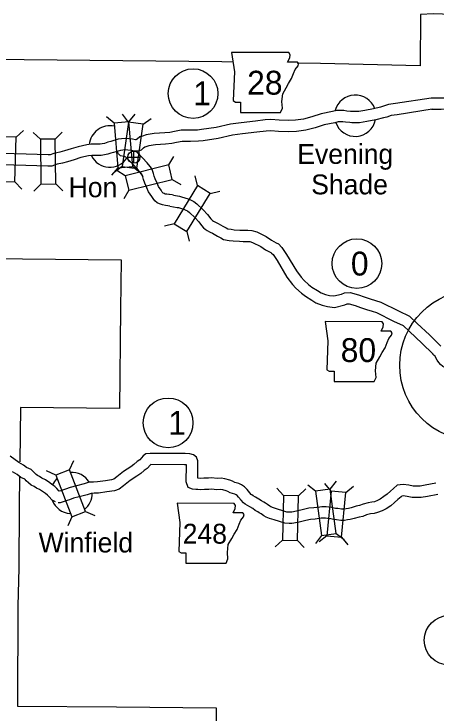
# Model space of a CAD drawing. Extents: x 1382482 to 1385815, y 1168351 to 1170484.
# Drawn here: x 1382910.5 to 1383022.7, y 1169947.1 to 1170133.1 of the extents above; entities that cross this region are included whole.
import ezdxf

# ---------------------------------------------------------------- set-up
doc = ezdxf.new("R2010")
doc.units = 0
for name, color, linetype in [('10', 7, 'Continuous'), ('20', 7, 'Continuous'), ('21', 7, 'Continuous'), ('24', 7, 'Continuous'), ('26', 7, 'Continuous'), ('8', 7, 'Continuous'), ('Default', 7, 'Continuous'), ('R_Draft', 7, 'Continuous')]:
    doc.layers.add(name, color=color, linetype=linetype)

msp = doc.modelspace()

# ---------------------------------------------------------------- linework, layer by layer
at = {"layer": '10'}
for points in [[(1383055.26, 1170107.05), (1383051.22, 1170107.22), (1383050.81, 1170107.46), (1383050.16, 1170107.88), (1383048.32, 1170109.4), (1383047.15, 1170110.4), (1383046.33, 1170111.03), (1383045.14, 1170111.68), (1383044.07, 1170112.06), (1383042.75, 1170112.27), (1383041.72, 1170112.17), (1383039.08, 1170112.1), (1383036.98, 1170112.15), (1383035.13, 1170111.99), (1383033.27, 1170111.77), (1383031.03, 1170111.4), (1383029.05, 1170111.26), (1383027.2, 1170111.01), (1383025.69, 1170110.79), (1383023.97, 1170110.76), (1383021.34, 1170110.78)], [(1383021.34, 1170110.78), (1383011.87, 1170109.34), (1383010.05, 1170109.08), (1383008.68, 1170108.63), (1383007.88, 1170108.39), (1383006.03, 1170107.91), (1383003.74, 1170107.49), (1383002.1, 1170107.2), (1383000.37, 1170107.24), (1382999.93, 1170107.26), (1382998.91, 1170107.35), (1382998.13, 1170107.46), (1382996.28, 1170107.45), (1382995.1, 1170107.19), (1382992.16, 1170106.61), (1382989.66, 1170105.78), (1382987.47, 1170105.21), (1382985.31, 1170104.93), (1382983.38, 1170104.81), (1382980.94, 1170104.94), (1382978.74, 1170105.12), (1382977.23, 1170104.99), (1382974.66, 1170104.68), (1382970.86, 1170104.23), (1382968.04, 1170103.86), (1382964.18, 1170103.01), (1382960.35, 1170102.43), (1382959.25, 1170102.3), (1382957.35, 1170102.24), (1382954.89, 1170102.22), (1382953.1, 1170101.95), (1382951.9, 1170101.65), (1382950.55, 1170101.54), (1382947.73, 1170101.37), (1382945.61, 1170100.98), (1382944.63, 1170100.68), (1382943.9, 1170100.45), (1382943.16, 1170099.9), (1382942.96, 1170099.76), (1382942.9, 1170099.72), (1382942.8, 1170099.72), (1382941.95, 1170099.84), (1382940.96, 1170099.98), (1382940.13, 1170100.02), (1382939.08, 1170099.93), (1382938.14, 1170099.84), (1382936.16, 1170099.21), (1382935.38, 1170099.06), (1382934.56, 1170098.76), (1382933.92, 1170098.64), (1382933.34, 1170098.52), (1382932.36, 1170098.55), (1382930.97, 1170098.5), (1382929.82, 1170098.37), (1382927.48, 1170097.87), (1382925.61, 1170097.28), (1382923.84, 1170096.76), (1382922.62, 1170096.43), (1382921.05, 1170096.09), (1382920.05, 1170095.71)], [(1383055.38, 1170104.04), (1383050.67, 1170104.24), (1383049.96, 1170104.47), (1383049.23, 1170104.91), (1383048.38, 1170105.46), (1383046.39, 1170107.1), (1383045.25, 1170108.07), (1383044.68, 1170108.51), (1383043.91, 1170108.93), (1383043.32, 1170109.14), (1383042.66, 1170109.25), (1383041.9, 1170109.17), (1383039.08, 1170109.1), (1383037.07, 1170109.14), (1383035.43, 1170109), (1383033.69, 1170108.8), (1383031.38, 1170108.41), (1383029.35, 1170108.27), (1383027.61, 1170108.04), (1383025.94, 1170107.8), (1383023.99, 1170107.75), (1383021.43, 1170107.78)], [(1383021.67, 1170107.8), (1383012.31, 1170106.38), (1383010.74, 1170106.14), (1383009.57, 1170105.76), (1383008.68, 1170105.5), (1383006.68, 1170104.98), (1383004.27, 1170104.54), (1383002.33, 1170104.19), (1383000.26, 1170104.24), (1382999.73, 1170104.27), (1382998.57, 1170104.37), (1382997.93, 1170104.46), (1382996.62, 1170104.46), (1382995.72, 1170104.25), (1382992.93, 1170103.7), (1382990.51, 1170102.9), (1382988.04, 1170102.26), (1382985.6, 1170101.94), (1382983.39, 1170101.81), (1382980.74, 1170101.95), (1382978.75, 1170102.11), (1382977.54, 1170102), (1382975.01, 1170101.7), (1382971.24, 1170101.26), (1382968.56, 1170100.9), (1382964.73, 1170100.06), (1382960.75, 1170099.46), (1382959.47, 1170099.31), (1382957.41, 1170099.24), (1382955.14, 1170099.22), (1382953.69, 1170099), (1382952.38, 1170098.68), (1382950.76, 1170098.55), (1382948.1, 1170098.38), (1382946.32, 1170098.06), (1382945.53, 1170097.82), (1382945.28, 1170097.74), (1382944.92, 1170097.47), (1382944.74, 1170097.35), (1382944.29, 1170096.99), (1382943.43, 1170096.71), (1382942.58, 1170096.72), (1382941.53, 1170096.87), (1382940.68, 1170096.99), (1382940.19, 1170097.01), (1382939.35, 1170096.94), (1382938.73, 1170096.89), (1382936.91, 1170096.31), (1382936.19, 1170096.16), (1382935.36, 1170095.86), (1382934.51, 1170095.7), (1382933.61, 1170095.51), (1382932.36, 1170095.55), (1382931.19, 1170095.5), (1382930.3, 1170095.41), (1382928.24, 1170094.97), (1382926.49, 1170094.41), (1382924.66, 1170093.87), (1382923.32, 1170093.51), (1382921.9, 1170093.21), (1382920.49, 1170092.67)], [(1382920.05, 1170095.69), (1382919.58, 1170095.71), (1382913.67, 1170095.86), (1382907.29, 1170096.03)], [(1382938.76, 1170095.46), (1382938.26, 1170096), (1382938.05, 1170096.29), (1382937.97, 1170096.39), (1382937.92, 1170096.45), (1382937.78, 1170096.57)], [(1382951.87, 1170082.1), (1382951.34, 1170082.19), (1382951.32, 1170082.19), (1382950.75, 1170082.24), (1382949.91, 1170082.38), (1382949.16, 1170082.66), (1382948.55, 1170082.96), (1382947.89, 1170083.48), (1382947.46, 1170084.06), (1382947.06, 1170084.63), (1382946.25, 1170085.84), (1382945.76, 1170086.95), (1382945.21, 1170088.22), (1382944.88, 1170089.11), (1382944.7, 1170089.82), (1382944.49, 1170090.37), (1382944.35, 1170090.66), (1382944.24, 1170090.83), (1382943.6, 1170091.54), (1382942.43, 1170092.86), (1382941.54, 1170093.74), (1382940.82, 1170094.48), (1382940.57, 1170094.76), (1382940.22, 1170095.08), (1382940.15, 1170095.13), (1382940.03, 1170095.16), (1382939.71, 1170095.28), (1382938.76, 1170095.46)], [(1382952.86, 1170084.95), (1382952.47, 1170085.04), (1382951.78, 1170085.15), (1382951.66, 1170085.17), (1382951.13, 1170085.22), (1382950.68, 1170085.29), (1382950.34, 1170085.42), (1382950.15, 1170085.51), (1382950.06, 1170085.58), (1382949.89, 1170085.82), (1382949.54, 1170086.32), (1382948.89, 1170087.29), (1382948.5, 1170088.15), (1382948, 1170089.33), (1382947.75, 1170090), (1382947.57, 1170090.72), (1382947.24, 1170091.57), (1382946.98, 1170092.12), (1382946.64, 1170092.65), (1382945.84, 1170093.54), (1382944.62, 1170094.92), (1382943.67, 1170095.86), (1382943.01, 1170096.53), (1382942.85, 1170096.71)], [(1382920.49, 1170092.67), (1382919.48, 1170092.72), (1382913.59, 1170092.86), (1382907.24, 1170093.03)], [(1382952.86, 1170084.95), (1382954.44, 1170084.69), (1382954.98, 1170084.56), (1382956.73, 1170084.01), (1382957.37, 1170083.77), (1382958.25, 1170083.33), (1382959.05, 1170082.69), (1382960.78, 1170081.11), (1382961.9, 1170079.84)], [(1382951.87, 1170082.1), (1382953.86, 1170081.74), (1382954.19, 1170081.67), (1382955.76, 1170081.17), (1382956.17, 1170081.01), (1382956.62, 1170080.79), (1382957.1, 1170080.41), (1382958.64, 1170079), (1382959.58, 1170077.94)], [(1382961.9, 1170079.84), (1382962.75, 1170078.73), (1382962.93, 1170078.48), (1382963.02, 1170078.42), (1382963.27, 1170078.25), (1382963.48, 1170078.11), (1382963.81, 1170077.9), (1382964.77, 1170077.47)], [(1382959.58, 1170077.94), (1382960.35, 1170076.93), (1382960.81, 1170076.31), (1382961.31, 1170075.95), (1382961.58, 1170075.77), (1382961.84, 1170075.6), (1382962.41, 1170075.24), (1382963.4, 1170074.8)], [(1382964.77, 1170077.47), (1382966, 1170076.73), (1382966.89, 1170076.32), (1382967.29, 1170076.08), (1382968.16, 1170075.92), (1382969.02, 1170075.8), (1382970.47, 1170075.72), (1382971.5, 1170075.71), (1382972.61, 1170075.67), (1382973.71, 1170075.6), (1382974.99, 1170075.22), (1382977.54, 1170073.99), (1382978.94, 1170073.05), (1382980.16, 1170072.34), (1382980.74, 1170072.04), (1382981.67, 1170071.11), (1382982.94, 1170069.26), (1382985.53, 1170064.87), (1382986.84, 1170063.18), (1382987.57, 1170062.33), (1382988.8, 1170061.23), (1382989.65, 1170060.58), (1382991.18, 1170059.63), (1382992.09, 1170059.07), (1382993.25, 1170058.6), (1382994.38, 1170058.36), (1382995.51, 1170058.19), (1382997.52, 1170058.68), (1382998.36, 1170059.02), (1382999.82, 1170059.15), (1383002.08, 1170058.5), (1383003.58, 1170057.96), (1383005.13, 1170057.43), (1383006.58, 1170057), (1383007.95, 1170056.57), (1383012.66, 1170054.24), (1383015.64, 1170052.82), (1383017.69, 1170050.91), (1383020.97, 1170047.85), (1383023.98, 1170044.86)], [(1382963.23, 1170074.89), (1382964.6, 1170074.07), (1382965.47, 1170073.67), (1382966.2, 1170073.22), (1382967.69, 1170072.95), (1382968.75, 1170072.81), (1382970.37, 1170072.73), (1382971.42, 1170072.71), (1382972.46, 1170072.67), (1382973.18, 1170072.63), (1382973.91, 1170072.41), (1382976.05, 1170071.38), (1382977.35, 1170070.5), (1382978.7, 1170069.72), (1382978.93, 1170069.6), (1382979.36, 1170069.18), (1382980.41, 1170067.65), (1382983.04, 1170063.18), (1382984.52, 1170061.28), (1382985.42, 1170060.23), (1382986.88, 1170058.92), (1382987.94, 1170058.11), (1382989.6, 1170057.08), (1382990.74, 1170056.38), (1382992.36, 1170055.73), (1382993.84, 1170055.4), (1382995.65, 1170055.14), (1382998.44, 1170055.82), (1382999.07, 1170056.07), (1382999.53, 1170056.11), (1383001.15, 1170055.65), (1383002.58, 1170055.13), (1383004.22, 1170054.57), (1383005.71, 1170054.13), (1383006.83, 1170053.78), (1383011.35, 1170051.54), (1383013.93, 1170050.31), (1383015.64, 1170048.71), (1383018.89, 1170045.69), (1383021.86, 1170042.73)], [(1383048.25, 1170025.19), (1383036.79, 1170025.48), (1383036.15, 1170025.79), (1383035.57, 1170026.18), (1383035.18, 1170026.91), (1383034.99, 1170027.48), (1383034.91, 1170028.23), (1383035.25, 1170038.52), (1383035.26, 1170038.65), (1383035.26, 1170038.65), (1383035.14, 1170038.66), (1383034.05, 1170038.68), (1383026.55, 1170038.83), (1383025.85, 1170038.85), (1383025.14, 1170039.1), (1383024.46, 1170039.43), (1383023.88, 1170040.01), (1383023.42, 1170040.48), (1383023.01, 1170041.13), (1383022.64, 1170041.78), (1383022.41, 1170042.19), (1383022.21, 1170042.41), (1383021.92, 1170042.68), (1383021.73, 1170042.85)], [(1382922.5, 1170006.29), (1382921.86, 1170006.99), (1382921.32, 1170007.54), (1382920.52, 1170008.13), (1382919.98, 1170008.49), (1382918.8, 1170009.34), (1382917.86, 1170009.79), (1382917.22, 1170010.18), (1382916.68, 1170010.45), (1382916.34, 1170010.75), (1382915.89, 1170011.16), (1382915.58, 1170011.52), (1382914.98, 1170012.09), (1382913.76, 1170012.59), (1382912.94, 1170013.21), (1382911.7, 1170013.96), (1382909.47, 1170015.58)], [(1382992.3, 1170002.16), (1382991.75, 1170002.09), (1382990.18, 1170001.88), (1382988.89, 1170001.77), (1382987.4, 1170001.46), (1382985.59, 1170001.03), (1382984.29, 1170000.75), (1382984.09, 1170000.71), (1382983.74, 1170000.72), (1382983, 1170000.76), (1382981.92, 1170001.11), (1382980.5, 1170001.53), (1382979.43, 1170001.88), (1382978.75, 1170002.15), (1382978.44, 1170002.32), (1382977.86, 1170002.73), (1382977.31, 1170003.1), (1382976.84, 1170003.39), (1382976.22, 1170003.75), (1382975.54, 1170004.21), (1382974.65, 1170004.74), (1382974.06, 1170005.05), (1382973.69, 1170005.3), (1382973.53, 1170005.42), (1382973.12, 1170005.9), (1382972.42, 1170006.73), (1382971.76, 1170007.45), (1382970.91, 1170008.04), (1382970.2, 1170008.32), (1382969.16, 1170008.66), (1382968.59, 1170008.97), (1382967.82, 1170009.28), (1382966.5, 1170009.61), (1382965.52, 1170009.74), (1382964.43, 1170009.72), (1382962.99, 1170009.82), (1382962.14, 1170009.78), (1382960.97, 1170009.77), (1382960.08, 1170009.7), (1382959.44, 1170009.74), (1382959.29, 1170009.74), (1382959.36, 1170014.41), (1382958.98, 1170015.36), (1382958.18, 1170016.01), (1382957.22, 1170016.22), (1382955.93, 1170016.33), (1382946.7, 1170016.37), (1382945.54, 1170016.24), (1382944.81, 1170015.69), (1382943.87, 1170014.62), (1382943.23, 1170014.16), (1382942.33, 1170013.39), (1382941.49, 1170012.82), (1382939.58, 1170011.56), (1382937.79, 1170010.13), (1382936.97, 1170009.55), (1382936.41, 1170009.33), (1382934.74, 1170009.07), (1382932.64, 1170008.79), (1382931.61, 1170008.75), (1382930.45, 1170008.67), (1382929.07, 1170008.26), (1382927.09, 1170007.72), (1382925.36, 1170007.32), (1382924.13, 1170006.85), (1382923.6, 1170006.65), (1382922.9, 1170006.41), (1382922.5, 1170006.3)], [(1382992.58, 1169999.17), (1382992.14, 1169999.11), (1382990.5, 1169998.9), (1382989.33, 1169998.8), (1382988.05, 1169998.53), (1382986.26, 1169998.1), (1382984.86, 1169997.8), (1382984.32, 1169997.71), (1382983.63, 1169997.73), (1382982.45, 1169997.78), (1382981.03, 1169998.24), (1382979.61, 1169998.67), (1382978.41, 1169999.05), (1382977.47, 1169999.43), (1382976.85, 1169999.77), (1382976.14, 1170000.26), (1382975.67, 1170000.59), (1382975.31, 1170000.81), (1382974.62, 1170001.2), (1382973.93, 1170001.68), (1382973.19, 1170002.12), (1382972.52, 1170002.47), (1382971.96, 1170002.85), (1382971.46, 1170003.22), (1382970.83, 1170003.97), (1382970.17, 1170004.75), (1382969.78, 1170005.17), (1382969.49, 1170005.37), (1382969.18, 1170005.5), (1382967.95, 1170005.89), (1382967.29, 1170006.26), (1382966.9, 1170006.42), (1382965.94, 1170006.66), (1382965.36, 1170006.74), (1382964.35, 1170006.71), (1382962.96, 1170006.81), (1382962.22, 1170006.78), (1382961.11, 1170006.77), (1382960.1, 1170006.69), (1382959.37, 1170006.74), (1382958.78, 1170006.72), (1382957.89, 1170006.82), (1382956.78, 1170007.26), (1382956.27, 1170008.79), (1382956.34, 1170013.28), (1382955.8, 1170013.33), (1382946.87, 1170013.37), (1382946.76, 1170013.36), (1382945.9, 1170012.38), (1382945.08, 1170011.79), (1382944.15, 1170011), (1382943.15, 1170010.33), (1382941.35, 1170009.14), (1382939.6, 1170007.73), (1382938.4, 1170006.89), (1382937.2, 1170006.41), (1382935.17, 1170006.1), (1382932.9, 1170005.79), (1382931.76, 1170005.75), (1382930.98, 1170005.7), (1382929.9, 1170005.38), (1382927.82, 1170004.81), (1382926.24, 1170004.44), (1382925.2, 1170004.04), (1382924.62, 1170003.83), (1382923.79, 1170003.54), (1382922.75, 1170003.26), (1382922.2, 1170003.26)], [(1382921.47, 1170003.44), (1382920.63, 1170003.89), (1382919.68, 1170004.93), (1382919.34, 1170005.27), (1382918.8, 1170005.68), (1382918.27, 1170006.03), (1382917.27, 1170006.75), (1382916.44, 1170007.14), (1382915.78, 1170007.54), (1382914.99, 1170007.94), (1382914.33, 1170008.52), (1382913.73, 1170009.08), (1382913.4, 1170009.45), (1382913.32, 1170009.53), (1382912.27, 1170009.97), (1382911.26, 1170010.73), (1382910.04, 1170011.46)], [(1383022.59, 1170008.41), (1383019.78, 1170007.88), (1383018.48, 1170007.61), (1383017.71, 1170007.64), (1383016.61, 1170007.61), (1383015.47, 1170007.88), (1383013.97, 1170008.06), (1383012.32, 1170007.88), (1383011.39, 1170007.07), (1383010.53, 1170006.33), (1383009.66, 1170005.55), (1383008.82, 1170004.86), (1383007.85, 1170004.21), (1383007.1, 1170003.81), (1383006.28, 1170003.51), (1383005.63, 1170003.37), (1383004.61, 1170003.2), (1383003.27, 1170002.86), (1383002.28, 1170002.49), (1383001.46, 1170002.29), (1383000.14, 1170001.9), (1382999.39, 1170001.72), (1382998.79, 1170001.66), (1382998.06, 1170001.54), (1382997.54, 1170001.53), (1382996.6, 1170001.67), (1382995.92, 1170001.74), (1382994.84, 1170001.98)], [(1383023.14, 1170005.46), (1383020.36, 1170004.93), (1383018.74, 1170004.6), (1383017.69, 1170004.64), (1383016.28, 1170004.61), (1383014.95, 1170004.93), (1383013.96, 1170005.04), (1383013.58, 1170005), (1383013.36, 1170004.81), (1383012.52, 1170004.08), (1383011.62, 1170003.27), (1383010.61, 1170002.45), (1383009.4, 1170001.63), (1383008.33, 1170001.06), (1383007.12, 1170000.62), (1383006.18, 1170000.42), (1383005.23, 1170000.26), (1383004.17, 1169999.99), (1383003.17, 1169999.62), (1383002.24, 1169999.39), (1383000.92, 1169999.01), (1382999.88, 1169998.75), (1382999.17, 1169998.69), (1382998.34, 1169998.55), (1382997.36, 1169998.52), (1382996.23, 1169998.69), (1382995.45, 1169998.77), (1382994.28, 1169999.03)], [(1382993.46, 1170002.12), (1382992.3, 1170002.16)], [(1382994.84, 1170001.98), (1382993.46, 1170002.12)], [(1382993.3, 1169999.12), (1382992.32, 1169999.16)], [(1382993.3, 1169999.12), (1382992.32, 1169999.16)], [(1382994.45, 1169999), (1382993.21, 1169999.13)]]:
    msp.add_lwpolyline(points, dxfattribs=at)
at = {"layer": '20'}
for p, q in [((1382940.91, 1170104.39), (1382939.33, 1170106.5)), ((1382941, 1170104.46), (1382942.7, 1170106.48)), ((1382937.06, 1170104.12), (1382935.04, 1170105.82)), ((1382941.01, 1170104.37), (1382941, 1170104.46)), ((1382944.83, 1170103.82), (1382946.94, 1170105.39)), ((1382911.03, 1170100.37), (1382912.95, 1170102.19)), ((1382917.46, 1170099.83), (1382915.57, 1170101.67)), ((1382921.42, 1170099.88), (1382923.26, 1170101.77)), ((1382951.58, 1170093.01), (1382952.94, 1170095.27)), ((1382938.08, 1170092.28), (1382936.38, 1170090.26)), ((1382939.2, 1170092.63), (1382937.08, 1170091.05)), ((1382940.05, 1170090.14), (1382937.79, 1170091.5)), ((1382942.03, 1170092.62), (1382944.05, 1170090.92)), ((1382943.11, 1170092.06), (1382944.69, 1170089.94)), ((1382959.22, 1170087.54), (1382958.61, 1170090.1)), ((1382910.71, 1170088.5), (1382912.53, 1170086.58)), ((1382917.61, 1170087.95), (1382915.77, 1170086.06)), ((1382921.57, 1170088), (1382923.46, 1170086.15)), ((1382952.53, 1170089.17), (1382954.8, 1170087.81)), ((1382941.01, 1170086.29), (1382939.65, 1170084.03)), ((1382962.6, 1170085.47), (1382965.17, 1170086.08)), ((1382953.02, 1170077.41), (1382950.45, 1170076.79)), ((1382956.4, 1170075.34), (1382957.01, 1170072.77)), ((1382925.24, 1170012.03), (1382926.32, 1170014.44)), ((1382921.55, 1170010.61), (1382919.13, 1170011.69)), ((1382990.63, 1170006.32), (1382988.54, 1170007.93)), ((1382994.76, 1170006.31), (1382993.08, 1170008.35)), ((1382994.56, 1170006.85), (1382996.16, 1170008.95)), ((1382998.7, 1170005.93), (1383000.74, 1170007.61)), ((1382982.15, 1170005.21), (1382980.33, 1170007.12)), ((1382986.11, 1170005.1), (1382988.02, 1170006.92)), ((1382994.74, 1170005.5), (1382994.56, 1170006.85)), ((1382929.5, 1170000.94), (1382931.91, 1169999.87)), ((1382925.81, 1169999.52), (1382924.73, 1169997.11)), ((1382992.22, 1169994.55), (1382990.61, 1169992.45)), ((1382993.61, 1169994.49), (1382991.57, 1169992.81)), ((1382996.14, 1169995.08), (1382998.24, 1169993.47)), ((1382981.84, 1169993.33), (1382979.92, 1169991.51)), ((1382985.8, 1169993.23), (1382987.61, 1169991.31)), ((1382997.55, 1169994.11), (1382999.23, 1169992.07))]:
    msp.add_line(p, q, dxfattribs=at)
for points in [[(1382937.06, 1170104.12), (1382938.08, 1170092.28), (1382942.03, 1170092.62), (1382941, 1170104.46)], [(1382940.91, 1170104.39), (1382939.2, 1170092.63), (1382943.11, 1170092.06), (1382944.83, 1170103.82)], [(1382910.71, 1170088.5), (1382911.03, 1170100.37), (1382907.07, 1170100.48), (1382906.75, 1170088.6)], [(1382921.57, 1170088), (1382921.42, 1170099.88), (1382917.46, 1170099.83), (1382917.61, 1170087.95)], [(1382951.58, 1170093.01), (1382940.05, 1170090.14), (1382941.01, 1170086.29), (1382952.53, 1170089.17)], [(1382956.4, 1170075.34), (1382962.6, 1170085.47), (1382959.22, 1170087.54), (1382953.02, 1170077.41)], [(1382929.5, 1170000.94), (1382925.24, 1170012.03), (1382921.55, 1170010.61), (1382925.81, 1169999.52)], [(1382996.14, 1169995.08), (1382994.56, 1170006.85), (1382990.63, 1170006.32), (1382992.22, 1169994.55)], [(1382994.76, 1170006.31), (1382993.61, 1169994.49), (1382997.55, 1169994.11), (1382998.7, 1170005.93)], [(1382982.15, 1170005.21), (1382981.84, 1169993.33), (1382985.8, 1169993.23), (1382986.11, 1170005.1)]]:
    msp.add_lwpolyline(points, close=True, dxfattribs=at)
at = {"layer": '21'}
for points in [[(1382968.29, 1170122.88), (1382969.05, 1170117.81), (1382968.71, 1170110.11), (1382969.39, 1170109.69), (1382970.66, 1170109.69), (1382970.66, 1170106.98), (1382981.31, 1170106.98), (1382981.82, 1170108.08), (1382981.65, 1170109.86), (1382981.91, 1170111.89), (1382982.84, 1170113.49), (1382983.43, 1170114.68), (1382984.27, 1170115.95), (1382984.78, 1170117.3), (1382985.21, 1170118.4), (1382985.97, 1170119.33), (1382986.14, 1170119.92), (1382985.8, 1170120.35), (1382983.18, 1170120.35), (1382983.77, 1170121.53), (1382983.85, 1170122.29), (1382983.5, 1170122.88)], [(1382993.17, 1170051.37), (1382993.93, 1170046.29), (1382993.59, 1170038.6), (1382994.27, 1170038.17), (1382995.54, 1170038.17), (1382995.54, 1170035.47), (1383006.2, 1170035.47), (1383006.71, 1170036.57), (1383006.54, 1170038.34), (1383006.79, 1170040.37), (1383007.72, 1170041.98), (1383008.31, 1170043.16), (1383009.16, 1170044.43), (1383009.67, 1170045.79), (1383010.09, 1170046.89), (1383010.85, 1170047.82), (1383011.02, 1170048.41), (1383010.68, 1170048.83), (1383008.06, 1170048.83), (1383008.65, 1170050.02), (1383008.74, 1170050.78), (1383008.38, 1170051.36)], [(1382953.81, 1170003.09), (1382954.57, 1169998.02), (1382954.24, 1169990.32), (1382954.91, 1169989.9), (1382956.18, 1169989.9), (1382956.18, 1169987.19), (1382966.84, 1169987.19), (1382967.35, 1169988.29), (1382967.18, 1169990.06), (1382967.43, 1169992.1), (1382968.36, 1169993.7), (1382968.95, 1169994.89), (1382969.8, 1169996.16), (1382970.31, 1169997.51), (1382970.73, 1169998.61), (1382971.49, 1169999.54), (1382971.66, 1170000.13), (1382971.32, 1170000.55), (1382968.7, 1170000.55), (1382969.29, 1170001.74), (1382969.38, 1170002.5), (1382969.03, 1170003.08)]]:
    msp.add_lwpolyline(points, close=True, dxfattribs=at)
at = {"layer": '24'}
for centre, start, end in [((1383001.19, 1170106.11), 19.7365, 165.9493), ((1383001.19, 1170106.11), 198.8444, 349.0616), ((1382935.94, 1170097.93), 77.4464, 174.6487), ((1382935.94, 1170097.93), 206.7402, 325.9508), ((1382925.78, 1170005.83), 31.2792, 93.8868), ((1382925.78, 1170005.83), 136.1215, 156.7913), ((1382925.78, 1170005.83), 307.8575, 359.2624), ((1382925.78, 1170005.83), 200.6803, 265.4216)]:
    msp.add_arc(centre, 5.5, start, end, dxfattribs=at)
at = {"layer": '26'}
for p, q in [((1382940.69, 1170095.08), (1382943.94, 1170095.08)), ((1382942.31, 1170093.46), (1382942.31, 1170096.71))]:
    msp.add_line(p, q, dxfattribs=at)
msp.add_circle((1382942.31, 1170095.08), 1.62, dxfattribs=at)
at = {"layer": '8'}
for points in [[(1383021.95, 1170133.14), (1383018.58, 1170132.97), (1383018.43, 1170119.37), (1382991.96, 1170119.96), (1382986.17, 1170120.06)], [(1383046.44, 1170132.28), (1383043.82, 1170132.34), (1383043.61, 1170132.37), (1383021.95, 1170133.14)], [(1382968.68, 1170120.37), (1382965.72, 1170120.42), (1382939.36, 1170120.69), (1382913.16, 1170120.94), (1382886.55, 1170121.29), (1382863.66, 1170121.42), (1382863.44, 1170108.2), (1382863.24, 1170094.33)], [(1382863.06, 1170081.8), (1382862.8, 1170068.57), (1382886, 1170068.34), (1382912.68, 1170068.11), (1382938.92, 1170067.81), (1382938.79, 1170054.68), (1382938.48, 1170028.27), (1382912.16, 1170028.59), (1382911.99, 1170014.09)], [(1382911.95, 1170010.32), (1382911.86, 1170002.22), (1382911.73, 1169985.81)], [(1382911.73, 1169985.81), (1382911.46, 1169975.84), (1382911.38, 1169949.22), (1382937.71, 1169949.01), (1382964.23, 1169948.71), (1382964.04, 1169921.98), (1382963.91, 1169895.42), (1382990.4, 1169895.36), (1382997.27, 1169895.4), (1382997.21, 1169901.93), (1383016.97, 1169901.86), (1383016.83, 1169894.77)]]:
    msp.add_lwpolyline(points, dxfattribs=at)
at = {"layer": 'Default'}
for centre in [(1382958.07, 1170111.97), (1383001.63, 1170066.8), (1382951.44, 1170024.47), (1383026.12, 1169966.68)]:
    msp.add_circle(centre, 6.6, dxfattribs=at)
at = {"layer": 'R_Draft'}
msp.add_circle((1383033, 1170039.77), 20, dxfattribs=at)

# ---------------------------------------------------------------- texts
at = {"layer": '21'}
for s, height, p in [('28', 6.336, (1382972.43, 1170111.71)), ('80', 6.336, (1382997.32, 1170040.64)), ('248', 5.28, (1382955.31, 1169992.37))]:
    msp.add_text(s, height=height, dxfattribs=at).set_placement(p)
at = {"layer": '24'}
for s, p in [('Evening', (1382985.77, 1170093.3)), ('Hon', (1382924.98, 1170084.44)), ('Shade', (1382989.47, 1170085.2)), ('Winfield', (1382917, 1169990.02))]:
    msp.add_text(s, height=5.28, dxfattribs=at).set_placement(p)
at = {"layer": 'Default'}
for s, p in [('1', (1382958.09, 1170108.88)), ('0', (1383000.02, 1170063.63)), ('1', (1382951.44, 1170021.3))]:
    msp.add_text(s, height=6.34, dxfattribs=at).set_placement(p)

doc.saveas('drawing.dxf')
